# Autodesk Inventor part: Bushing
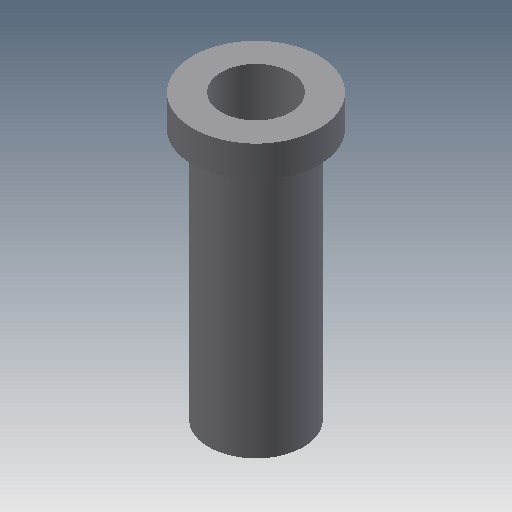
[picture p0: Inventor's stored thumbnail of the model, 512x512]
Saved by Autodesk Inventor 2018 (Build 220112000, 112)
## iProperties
Shininess: 77.0
Length Units: 11269
Angle Units: 11279
Time Units: 11290
Mass Units: 11283
Length Display Precision: 3
Angle Display Precision: 2
Created: 2002-02
Part Number: Bushing
Document SubType Name: Modeling
Designer: ***
Density: 1 g/cm^3
Material: Generic
Appearance: Default
Density: 0.0
Volumn: 0.0
Area: 0.0
PropertySet Name: Model Information
Control State: 0
Master: False
Checked Out: False
Author: ***
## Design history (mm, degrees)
sketch "Sketch2"
  geometry: C1 r 10 at (0, 0); 1 further point
  constraints: 1 centre point, 1 coincident
  dimensions: "d8" = 20 diameter of C1
extrude "Extrusion1" new body sketch "Sketch2" distance "d6" = 5; taper "d7" = 0 deg
sketch "Sketch4"
  geometry: C1 r 7.5 at (0, 0); 1 further point
  constraints: 1 centre point, 1 coincident
  dimensions: "d9" = 15 diameter of C1
extrude "Extrusion2" join sketch "Sketch4" distance "d10" = 40; taper "d11" = 0 deg
sketch "Sketch5"
  geometry: C1 r 5.5 at (0, 0); 1 further point
  constraints: 1 centre point, 1 coincident
  dimensions: "d12" = 11 diameter of C1
extrude "Extrusion3" cut sketch "Sketch5" distance "d13" = 57.75; taper "d14" = 0 deg
body "Solid2"
